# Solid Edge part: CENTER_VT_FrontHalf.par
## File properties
Author: haileyy
Template: ansi part.par
Last saved by: haileyy
Revision: 1
Application: Solid Edge
Accuracy: 0.990
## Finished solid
Body 1: solid body, 37 faces, 105 edges, 70 vertices.
  Faces by surface: plane 19, cylinder 12, swept 6
  Edges by curve: line 69, circle 24, spline 12
Bounding box of the edges (mm; curved faces can reach further): 139.416 x 36.588 x 3.175, from (-131.5411, 258.3359, -3.175) to (7.8749, 294.9237, 0).
Cylindrical faces by radius (mm): R6.35 x8, R204.8272 x1, R222.7524 x1, R650.0012 x1, R657.3125 x1
Planar faces by outward normal: +x 6, +y 3, +z 1, -x 3, -y 3, -z 1, oblique 2
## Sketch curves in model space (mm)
spline (-131.5411, 274.9788, 0) -> (-123.029, 268.1599, 0) -> (-112.4402, 264.607, 0)
spline (-9.0943, 258.9744, 0) -> (-5.146, 259.1329, 0) -> (-1.1982, 259.3044, 0)
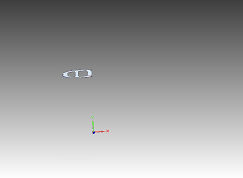
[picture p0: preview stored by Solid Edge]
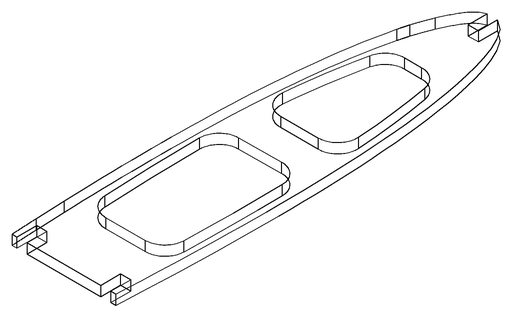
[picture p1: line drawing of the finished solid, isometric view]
